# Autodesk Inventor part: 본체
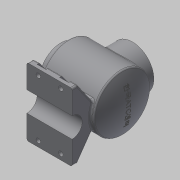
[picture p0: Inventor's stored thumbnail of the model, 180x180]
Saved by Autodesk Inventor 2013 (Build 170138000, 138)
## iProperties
Created: 2017-04
Part Number: 본체
Material: 일반
Document SubType Name: Modeling
Designer: Administrator
Density: 1 g/cm^3
Author: Administrator
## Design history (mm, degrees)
sketch "스케치1"
  geometry: L1 (0, 0)-(120, 0); L2 (0, 28)-(0, 38); L3 (0, 38)-(9, 38); L4 (12, 41)-(12, 47); L5 (15, 50)-(108.336, 50); L6 (1, 27)-(22, 27); L7 (22, 27)-(22, 37); L8 (25, 40)-(99.903, 40); L9 (1, 27)-(0, 28); A1 r 113 centre (7, 0) between (120, 0) and (108.336, 50); A2 r 103 centre (7, 0) between (110, 0) and (102.69, 38.11); A3 r 3 centre (25, 37) between (25, 40) and (22, 37); A4 r 3 centre (99.903, 37) between (102.69, 38.11) and (99.903, 40); A5 r 3 centre (15, 47) between (15, 50) and (12, 47); A6 r 3 centre (9, 41) between (9, 38) and (12, 41); 2 further points
  constraints: 18 end point, 13 point on circle, 8 tangent, 6 centre point, 6 point on line, 4 parallel, 3 equal radius, 3 perpendicular, 1 horizontal
  dimensions: "d0" = 120 distance of L1.start L1.end; "d1" = 226 diameter of A1; "d2" = 10 radial gap between concentric circles of A1 A2; "d4" = 100 diameter of L5 L1; "d5" = 76 diameter of L3 L1; "d6" = 54 diameter of L6 L1; "d7" = 80 diameter of L8 L1; "d8" = 22 distance between parallel lines of L7 L2; "d9" = 12 distance between parallel lines of L4 L2; "d10" = 3 radius of A3; "d11" = 1 distance of L6.start point (0, 27); "d12" = 1 distance of L2.start point (0, 27) (= d11)
revolve "회전1" sketch "스케치1" stored, may be unused: angle "d13" = 90 deg
node "작업 평면1"
sketch "스케치2"
  geometry: C1 r 38 at (-62, 0); 1 further point
  constraints: 1 centre point, 1 horizontal alignment
  dimensions: "d15" = 76 diameter of C1; "d17" = 62 distance of point (0, 0) C1.centre
extrude "돌출1" join sketch "스케치2" stored distance "d18" = 10; taper "d19" = 0 deg
fillet "모깎기1" dims "d20" = 3
sketch "스케치3"
  geometry: C1 r 38 at (0, 0) reference; C2 r 27 at (0, 0); 1 further point
  constraints: 1 centre point, 1 coincident
  dimensions: "d21" = 54 diameter of C2
extrude "돌출2" cut sketch "스케치3" stored distance "d23" = 10; taper "d24" = 0 deg
chamfer "모따기1" distance "d25" = 1; stored, may be unused: second distance "d26" = 2, angle "d27" = 45 deg
sketch "스케치4"
  geometry: C1 r 38 at (0, 0) reference; 1 further point
  constraints: 1 vertical alignment
  dimensions: "d28" = 32.5 distance of C1.centre point (0, 32.5)
hole "구멍1" sketch "스케치4" at (0, 32.5) diameter "d29" = 3.242; stored, may be unused: countersink angle "d33" = 90 deg, drill point angle "d35" = 118 deg; dims "d30" = 8, "d31" = 4, "d32" = 2, "d34" = 10
sketch "스케치5"
  geometry: C1 r 38 at (0, 0) reference; 2 further points
  constraints: 1 vertical alignment
  dimensions: "d39" = 32.5 distance of C1.centre point (0, 32.5)
hole "구멍2" sketch "스케치5" at (0, 32.5) diameter "d40" = 3.242; stored, may be unused: countersink angle "d44" = 90 deg, drill point angle "d46" = 118 deg; dims "d41" = 8, "d42" = 4, "d43" = 2, "d45" = 10
node "작업 평면2"
sketch "스케치6"
  geometry: L1 (-22, 60)-(-102, 60); L2 (-102, 60)-(-102, -60); L3 (-102, -60)-(-22, -60); L4 (-22, -60)-(-22, 60); L5 (-22, 60)-(-102, -60); L6 (-102, 60)-(-22, -60); C1 r 28 at (-62, 0) reference; 1 further point
  constraints: 12 end point, 2 midpoint, 2 parallel, 1 horizontal, 1 perpendicular
  dimensions: "d54" = 120 distance of L3.end L1.start; "d56" = 80 distance of L2.end L3.end
extrude "돌출3" join sketch "스케치6" distance "d57" = 10; taper "d58" = 0 deg
sketch "스케치7"
  geometry: L1 (120, 0)-(120, 10) reference; L2 (0, 10)-(120, 10) reference; L3 (0, 0)-(0, 10) reference; L4 (0, 10)-(38.416, 36.899); L5 (120, 10)-(81.584, 36.899); A1 r 50 centre (60, 82) between (38.416, 36.899) and (81.584, 36.899) reference; 1 further point
  constraints: 4 end point, 2 point on circle
  dimensions: "d59" = 55 deg angle of L3 L4; "d60" = 55 deg angle of L1 L5
extrude "돌출4" join sketch "스케치7" distance "d61" = 80; taper "d62" = 0 deg
fillet "모깎기2" dims "d63" = 3
fillet "모깎기3" dims "d64" = 3
sketch "스케치8"
  geometry: L1 (0, 0)-(114, 0) reference; C1 r 18 at (57, 0); A1 r 50 centre (57, 82) between (38.639, 35.493) and (75.361, 35.493) reference
  constraints: 1 centre point, 1 midpoint, 1 vertical alignment
  dimensions: "d65" = 36 diameter of C1
extrude "돌출5" cut sketch "스케치8" distance "d67" = 80; taper "d68" = 0 deg
sketch "스케치9"
  geometry: C1 r 28 at (62, 0) reference; C2 r 4 at (42, 50); 1 further point
  constraints: 1 centre point
  dimensions: "d71" = 8 diameter of C2; "d73" = 50 vertical distance of C1.centre C2.centre; "d74" = 20 horizontal distance of C1.centre C2.centre
extrude "돌출6" cut sketch "스케치9" distance "d75" = 6; taper "d76" = 0 deg
sketch "스케치10"
  geometry: L1 (-8, 0)-(-8, 10); L2 (-17, 10)-(57, 10) reference; L3 (-17, 10)-(57, 10) reference; L4 (8, 0)-(8, 10); C1 r 4 at (0, 0) reference; A1 r 8 centre (0, 0) between (-8, 0) and (8, 0); 1 further point
  constraints: 4 end point, 2 point on circle, 2 point on line, 2 tangent, 1 centre point, 1 coincident, 1 perpendicular, 1 vertical
  dimensions: "d77" = 16 diameter of A1
extrude "돌출7" cut sketch "스케치10" stored distance "d79" = 6; taper "d80" = 0 deg
node "작업 평면3"
sketch "스케치11"
  geometry: L1 (4.803, 33.183)-(4.803, -33.183); L2 (4.803, -33.183)-(-4.803, -33.183); L3 (-4.803, -33.183)-(-4.803, 33.183); L4 (-4.803, 33.183)-(4.803, 33.183); L5 (0, 33.183)-(0, -33.183); L6 (4.803, 0)-(-4.803, 0); 1 further point
  constraints: 6 midpoint, 4 end point, 2 other
feature "엠보싱1" sketch "스케치11" dims "d88" = 0.5, "d89" = 0
fillet "모깎기4" dims "d90" = 3
fillet "모깎기5" dims "d91" = 3
node "솔리드1"
pattern_circular "원형 패턴1" dims angle "d37" = 360 deg
pattern_circular "원형 패턴2" dims angle "d48" = 360 deg
pattern_linear "직사각형 패턴1" dims "d86" = 1
mirror "대칭1"
node "투영된 루프1"
other parameters: "d14" = 65, "d50" = -82
